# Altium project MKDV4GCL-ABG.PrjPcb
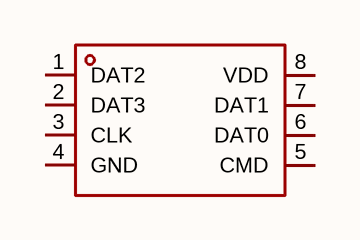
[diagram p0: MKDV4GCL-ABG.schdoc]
1 sheet, 1 parts. Net scope: global (net labels, ports and power ports of the same name join across sheets).

## Sheet MKDV4GCL-ABG.schdoc
size 127 x 101 mm

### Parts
U?  mkdv4gcl-abg  [LGA-8_L8.0-W6.0-P1.27-TL]  (value not drawn)

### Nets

Not connected (* = marked no-connect by the designer): U? 1(DAT2) 2(DAT3) 3(CLK) 4(GND) 5(CMD) 6(DAT0) 7(DAT1) 8(VDD)

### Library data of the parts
U? = mkdv4gcl-abg: 存储容量:4Gbit;时钟频率(fc):50MHz;工作电压:2.7V~3.6V;; Manufacturer: MK(米客方德); AddInBom: yes; ModelId: 2a1b5c5709a546a6a3c45eb13f6b3888; ModelTransform: 314.96,236.22,0,0,0,0,0,0,0; Memory Size: 4Gbit; Interface: SD接口；SPI; Clock Frequency: 50MHz; Standby Supply Current: 130uA; Program / Erase Cycles: 6万次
